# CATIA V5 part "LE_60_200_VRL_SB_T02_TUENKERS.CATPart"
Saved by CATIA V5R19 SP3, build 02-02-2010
Part number: LE_60_200_VRL_SB_T02_TUENKERS
Bounding box of the stored display mesh (mm): x -254.049 to 530.951, y -14.995 to 211.005, z 0 to 100
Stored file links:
  C:\Dokumente und Einstellungen\mitric\Desktop\LE_60_200_VRL_SB_T02_TUENKERS.CATPart
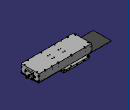
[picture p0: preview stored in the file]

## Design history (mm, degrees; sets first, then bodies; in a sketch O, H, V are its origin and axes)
AxisSystem1: origin (0, 0, 0), X (1, 0, 0), Y (0, 1, 0), Z (0, 0, 1)
Set1 "Platte"
  DatumSurface1 "Extrude.1"
  DatumSurface2 "Split.1"
Body1 "LE_60_VRL" (main body)
  Body2 "Product1.1\\DIN 912  (Regelgewinde) - ersetzt durch DIN EN ISO 4762 M6 x 35_1\\Volumenkörper1"
    Solid1 "Solid.1": solid without history
  Assemble1: tool Body2
  Body3 "Product1.1\\DIN 912  (Regelgewinde) - ersetzt durch DIN EN ISO 4762 M6 x 35_2\\Volumenkörper1"
    Solid2 "Solid.1": solid without history
  Assemble2: tool Body3
  Body4 "Product1.1\\DIN 912  (Regelgewinde) - ersetzt durch DIN EN ISO 4762 M6 x 35_3\\Volumenkörper1"
    Solid3 "Solid.1": solid without history
  Assemble3: tool Body4
  Body5 "Product1.1\\DIN 912  (Regelgewinde) - ersetzt durch DIN EN ISO 4762 M6 x 35_4\\Volumenkörper1"
    Solid4 "Solid.1": solid without history
  Assemble4: tool Body5
  Body6 "Product1.1\\DIN 912  (Regelgewinde) - ersetzt durch DIN EN ISO 4762 M6 x 35_5\\Volumenkörper1"
    Solid5 "Solid.1": solid without history
  Assemble5: tool Body6
  Body7 "Product1.1\\DIN 912  (Regelgewinde) - ersetzt durch DIN EN ISO 4762 M6 x 35_6\\Volumenkörper1"
    Solid6 "Solid.1": solid without history
  Assemble6: tool Body7
  Body8 "Product1.1\\DIN 912  (Regelgewinde) - ersetzt durch DIN EN ISO 4762 M6 x 35_7\\Volumenkörper1"
    Solid7 "Solid.1": solid without history
  Assemble7: tool Body8
  Body9 "Product1.1\\DIN 912  (Regelgewinde) - ersetzt durch DIN EN ISO 4762 M6 x 35_8\\Volumenkörper1"
    Solid8 "Solid.1": solid without history
  Assemble8: tool Body9
  Body10 "Product1.1\\DIN 912  (Regelgewinde) - ersetzt durch DIN EN ISO 4762 M6 x 25_1\\Volumenkörper1"
    Solid9 "Solid.1": solid without history
  Assemble9: tool Body10
  Body11 "Product1.1\\DIN 912  (Regelgewinde) - ersetzt durch DIN EN ISO 4762 M6 x 25_2\\Volumenkörper1"
    Solid10 "Solid.1": solid without history
  Assemble10: tool Body11
  Body12 "Product1.1\\DIN 912  (Regelgewinde) - ersetzt durch DIN EN ISO 4762 M6 x 25_3\\Volumenkörper1"
    Solid11 "Solid.1": solid without history
  Assemble11: tool Body12
  Body13 "Product1.1\\DIN 912  (Regelgewinde) - ersetzt durch DIN EN ISO 4762 M6 x 25_4\\Volumenkörper1"
    Solid12 "Solid.1": solid without history
  Assemble12: tool Body13
  Body14 "Product1.1\\DIN 912  (Regelgewinde) - ersetzt durch DIN EN ISO 4762 M6 x 25_5\\Volumenkörper1"
    Solid13 "Solid.1": solid without history
  Assemble13: tool Body14
  Body15 "Product1.1\\DIN 912  (Regelgewinde) - ersetzt durch DIN EN ISO 4762 M6 x 25_6\\Volumenkörper1"
    Solid14 "Solid.1": solid without history
  Assemble14: tool Body15
  Body16 "Product1.1\\DIN 912  (Regelgewinde) - ersetzt durch DIN EN ISO 4762 M6 x 25_7\\Volumenkörper1"
    Solid15 "Solid.1": solid without history
  Assemble15: tool Body16
  Body17 "Product1.1\\DIN 912  (Regelgewinde) - ersetzt durch DIN EN ISO 4762 M6 x 25_8\\Volumenkörper1"
    Solid16 "Solid.1": solid without history
  Assemble16: tool Body17
  Body18 "Product1.1\\DIN 912  (Regelgewinde) - ersetzt durch DIN EN ISO 4762 M6 x 25_9\\Volumenkörper1"
    Solid17 "Solid.1": solid without history
  Assemble17: tool Body18
  Body19 "Product1.1\\DIN 912  (Regelgewinde) - ersetzt durch DIN EN ISO 4762 M6 x 25_10\\Volumenkörper1"
    Solid18 "Solid.1": solid without history
  Assemble18: tool Body19
  Body20 "Product1.1\\DIN 912  (Regelgewinde) - ersetzt durch DIN EN ISO 4762 M6 x 25_11\\Volumenkörper1"
    Solid19 "Solid.1": solid without history
  Assemble19: tool Body20
  Body21 "Product1.1\\DIN 912  (Regelgewinde) - ersetzt durch DIN EN ISO 4762 M6 x 25_12\\Volumenkörper1"
    Solid20 "Solid.1": solid without history
  Assemble20: tool Body21
  Body22 "Product1.1\\DIN 912  (Regelgewinde) - ersetzt durch DIN EN ISO 4762 M12 x 30_1\\Volumenkörper1"
    Solid21 "Solid.1": solid without history
  Assemble21: tool Body22
  Body23 "Product1.1\\DIN 912  (Regelgewinde) - ersetzt durch DIN EN ISO 4762 M12 x 30_2\\Volumenkörper1"
    Solid22 "Solid.1": solid without history
  Assemble22: tool Body23
  Body24 "Product1.1\\200976 - Sicherungsscheibe S6 (Schnorr)_1\\Volumenkörper1"
    Solid23 "Solid.1": solid without history
  Assemble23: tool Body24
  Body25 "Product1.1\\200976 - Sicherungsscheibe S6 (Schnorr)_2\\Volumenkörper1"
    Solid24 "Solid.1": solid without history
  Assemble24: tool Body25
  Body26 "Product1.1\\200976 - Sicherungsscheibe S6 (Schnorr)_3\\Volumenkörper1"
    Solid25 "Solid.1": solid without history
  Assemble25: tool Body26
  Body27 "Product1.1\\200976 - Sicherungsscheibe S6 (Schnorr)_4\\Volumenkörper1"
    Solid26 "Solid.1": solid without history
  Assemble26: tool Body27
  Body28 "Product1.1\\200976 - Sicherungsscheibe S6 (Schnorr)_5\\Volumenkörper1"
    Solid27 "Solid.1": solid without history
  Assemble27: tool Body28
  Body29 "Product1.1\\200976 - Sicherungsscheibe S6 (Schnorr)_6\\Volumenkörper1"
    Solid28 "Solid.1": solid without history
  Assemble28: tool Body29
  Body30 "Product1.1\\200165 - Zylinderschraube M6 x 10 - DIN 912_1\\Volumenkörper1"
    Solid29 "Solid.1": solid without history
  Assemble29: tool Body30
  Body31 "Product1.1\\200165 - Zylinderschraube M6 x 10 - DIN 912_2\\Volumenkörper1"
    Solid30 "Solid.1": solid without history
  Assemble30: tool Body31
  Body32 "Product1.1\\200165 - Zylinderschraube M6 x 10 - DIN 912_3\\Volumenkörper1"
    Solid31 "Solid.1": solid without history
  Assemble31: tool Body32
  Body33 "Product1.1\\200165 - Zylinderschraube M6 x 10 - DIN 912_4\\Volumenkörper1"
    Solid32 "Solid.1": solid without history
  Assemble32: tool Body33
  Body34 "Product1.1\\200165 - Zylinderschraube M6 x 10 - DIN 912_5\\Volumenkörper1"
    Solid33 "Solid.1": solid without history
  Assemble33: tool Body34
  Body35 "Product1.1\\200165 - Zylinderschraube M6 x 10 - DIN 912_6\\Volumenkörper1"
    Solid34 "Solid.1": solid without history
  Assemble34: tool Body35
  Body36 "Product1.1\\DIN 912  (Regelgewinde) - ersetzt durch DIN EN ISO 4762 M6 x 30_8\\Volumenkörper1"
    Solid35 "Solid.1": solid without history
  Assemble35: tool Body36
  Body37 "Product1.1\\DIN 912  (Regelgewinde) - ersetzt durch DIN EN ISO 4762 M6 x 30_7\\Volumenkörper1"
    Solid36 "Solid.1": solid without history
  Assemble36: tool Body37
  Body38 "Product1.1\\DIN 912  (Regelgewinde) - ersetzt durch DIN EN ISO 4762 M6 x 30_6\\Volumenkörper1"
    Solid37 "Solid.1": solid without history
  Assemble37: tool Body38
  Body39 "Product1.1\\DIN 912  (Regelgewinde) - ersetzt durch DIN EN ISO 4762 M6 x 30_5\\Volumenkörper1"
    Solid38 "Solid.1": solid without history
  Assemble38: tool Body39
  Body40 "Product1.1\\DIN 912  (Regelgewinde) - ersetzt durch DIN EN ISO 4762 M6 x 30_4\\Volumenkörper1"
    Solid39 "Solid.1": solid without history
  Assemble39: tool Body40
  Body41 "Product1.1\\DIN 912  (Regelgewinde) - ersetzt durch DIN EN ISO 4762 M6 x 30_3\\Volumenkörper1"
    Solid40 "Solid.1": solid without history
  Assemble40: tool Body41
  Body42 "Product1.1\\DIN 912  (Regelgewinde) - ersetzt durch DIN EN ISO 4762 M6 x 30_2\\Volumenkörper1"
    Solid41 "Solid.1": solid without history
  Assemble41: tool Body42
  Body43 "Product1.1\\DIN 912  (Regelgewinde) - ersetzt durch DIN EN ISO 4762 M6 x 30_1\\Volumenkörper1"
    Solid42 "Solid.1": solid without history
  Assemble42: tool Body43
  Body44 "Product1.1\\276035 Sensor P+F NBB4-12GM30-E2-V1_1\\Volumenkörper1"
    Solid43 "Solid.1": solid without history
  Assemble43: tool Body44
  Body45 "Product1.1\\276035 Sensor P+F NBB4-12GM30-E2-V1_2\\Volumenkörper1"
    Solid44 "Solid.1": solid without history
  Assemble44: tool Body45
  Body46 "Product1.1\\276035 Sensor P+F NBB4-12GM30-E2-V1_3\\Volumenkörper1"
    Solid45 "Solid.1": solid without history
  Assemble45: tool Body46
  Body47 "Product1.1\\276035 Sensor P+F NBB4-12GM30-E2-V1_4\\Volumenkörper1"
    Solid46 "Solid.1": solid without history
  Assemble46: tool Body47
  Body48 "Product1.1\\Mutter M12 für Abfrage_1\\Volumenkörper1"
    Solid47 "Solid.1": solid without history
  Assemble47: tool Body48
  Body49 "Product1.1\\Mutter M12 für Abfrage_2\\Volumenkörper1"
    Solid48 "Solid.1": solid without history
  Assemble48: tool Body49
  Body50 "Product1.1\\Mutter M12 für Abfrage_3\\Volumenkörper1"
    Solid49 "Solid.1": solid without history
  Assemble49: tool Body50
  Body51 "Product1.1\\Mutter M12 für Abfrage_4\\Volumenkörper1"
    Solid50 "Solid.1": solid without history
  Assemble50: tool Body51
  Body52 "Product2.1\\251961 Abstimmplatte LE 60 Verstellung_1\\Volumenkörper1"
    Solid51 "Solid.1": solid without history
  Assemble51: tool Body52
  Body53 "Product2.1\\251961 Abstimmplatte LE 60 Verstellung_2\\Volumenkörper1"
    Solid52 "Solid.1": solid without history
  Assemble52: tool Body53
  Body54 "Product2.1\\276027 Anschlag LE 60-100 Standard _1\\Volumenkörper1"
    Solid53 "Solid.1": solid without history
  Assemble53: tool Body54
  Body55 "Product2.1\\276027 Anschlag LE 60-100 Standard _2\\Volumenkörper1"
    Solid54 "Solid.1": solid without history
  Assemble54: tool Body55
  Body56 "Product2.1\\255331 Seitenplatte LE 60-200_2\\Volumenkörper1"
    Solid55 "Solid.1": solid without history
  Assemble55: tool Body56
  Body57 "Product2.1\\255331 Seitenplatte LE 60-200_1\\Volumenkörper1"
    Solid56 "Solid.1": solid without history
  Assemble56: tool Body57
  Body58 "Product2.1\\255329 Platte LE 60 200_1\\Volumenkörper1"
    Solid57 "Solid.1": solid without history
  Assemble57: tool Body58
  Body59 "Product2.1\\251934 Platte LE 60 - 100_1\\Volumenkörper1"
    Solid58 "Solid.1": solid without history
  Assemble58: tool Body59
  Body60 "Product2.1\\251906 Platte LE 60 - 100-Verstellung_1\\Volumenkörper1"
    Solid59 "Solid.1": solid without history
  Assemble59: tool Body60
  Body61 "Product2.1\\255368 Puffer LE 60 -100-13,5 _2\\Volumenkörper1"
    Solid60 "Solid.1": solid without history
  Assemble60: tool Body61
  Body62 "Product2.1\\255368 Puffer LE 60 -100-13,5 _1\\Volumenkörper1"
    Solid61 "Solid.1": solid without history
  Assemble61: tool Body62
Body63 "SB"
  Solid62: solid without history
Body64 "SB"
  Solid63 "Solid.1": solid without history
